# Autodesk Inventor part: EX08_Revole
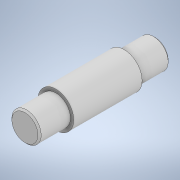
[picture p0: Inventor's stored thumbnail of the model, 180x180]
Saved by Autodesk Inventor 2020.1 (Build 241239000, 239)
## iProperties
Created: 2019-10
Part Number: EX08_Revole
Material: Generic
Document SubType Name: Modeling
Designer: Synergysoft Dell02
Density: 1 g/cm^3
Appearance: Default
Author: Synergysoft Dell02
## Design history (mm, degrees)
sketch "Sketch1"
  geometry: L1 (0, 40)-(9, 40); L2 (9, 40)-(9, 21); L3 (9, 21)-(11, 21); L4 (11, 21)-(11, -21); L5 (11, -21)-(9, -21); L6 (9, -21)-(9, -40); L7 (9, -40)-(0, -40); L8 (0, -40)-(0, 40); 3 further points
  constraints: 16 end point, 6 perpendicular, 2 midpoint, 2 point on line, 1 coincident, 1 horizontal, 1 horizontal alignment
  dimensions: "d0" = 18 diameter of L2 L8; "d1" = 22 diameter of L4 L8; "d2" = 42 distance between parallel lines of L5 L3; "d3" = 80 distance between parallel lines of L7 L1
revolve "Revolution1" sketch "Sketch1" stored, may be unused: angle "d4" = 360 deg
sketch "Sketch2"
  geometry: L1 (15, 5)-(5, 5); L2 (5, 5)-(5, -5); L3 (5, -5)-(15, -5); L4 (15, -5)-(15, 5); L5 (0, -56)-(0, 56) reference; 2 further points
  constraints: 8 end point, 2 parallel, 1 horizontal, 1 horizontal alignment, 1 midpoint, 1 perpendicular
  dimensions: "d5" = 10 distance of L3.end L2.end; "d6" = 10 distance of L2.end L1.end; "d8" = 5 distance from line of L2 point (0, 0)
revolve "Revolution2" sketch "Sketch2" stored, may be unused: angle "d9" = 90 deg
chamfer "Chamfer1" distance "d10" = 1; stored, may be unused: second distance "d11" = 2, angle "d12" = 45 deg
body "Solid1"
